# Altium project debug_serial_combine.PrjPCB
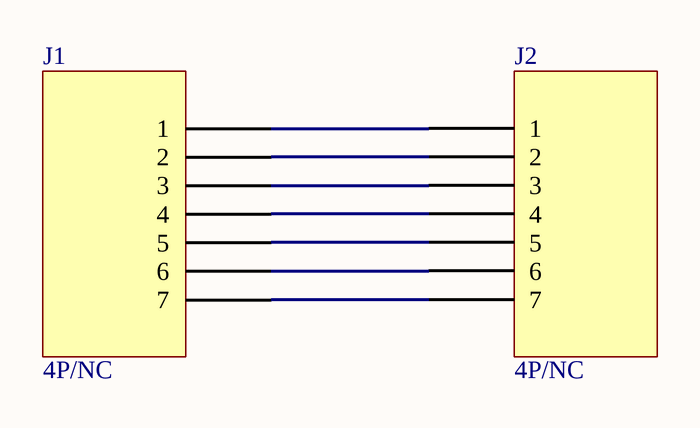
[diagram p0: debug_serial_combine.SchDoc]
1 sheet, 2 parts. Net scope: global (net labels, ports and power ports of the same name join across sheets).
Board file: debug_serial_combine.PcbDoc

## Sheet debug_serial_combine.SchDoc: Smartplug
size A3

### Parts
J1  4P/NC  [HDR1X7]
J2  4P/NC  [HDR1X7]

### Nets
NetJ1_1: J1.1 J2.1
NetJ1_2: J1.2 J2.2
NetJ1_3: J1.3 J2.3
NetJ1_4: J1.4 J2.4
NetJ1_5: J1.5 J2.5
NetJ1_6: J1.6 J2.6
NetJ1_7: J1.7 J2.7

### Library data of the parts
J1 J2 = Header 7: 接口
